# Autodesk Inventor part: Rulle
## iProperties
Created: 2001-12
Part Number: Rulle
Material: Aluminum-6061
Document SubType Name: Modeling
Designer: Tobben
Control State: 0
Master: False
Checked Out: False
Shininess: 64.0
Length Units: 11269
Angle Units: 11279
Time Units: 11290
Mass Units: 11283
Length Display Precision: 3
Angle Display Precision: 2
Density: 0.0
Volumn: 0.0
Area: 0.0
PropertySet Name: Model Information
Author: Tobben
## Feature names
1. Extrusion1
